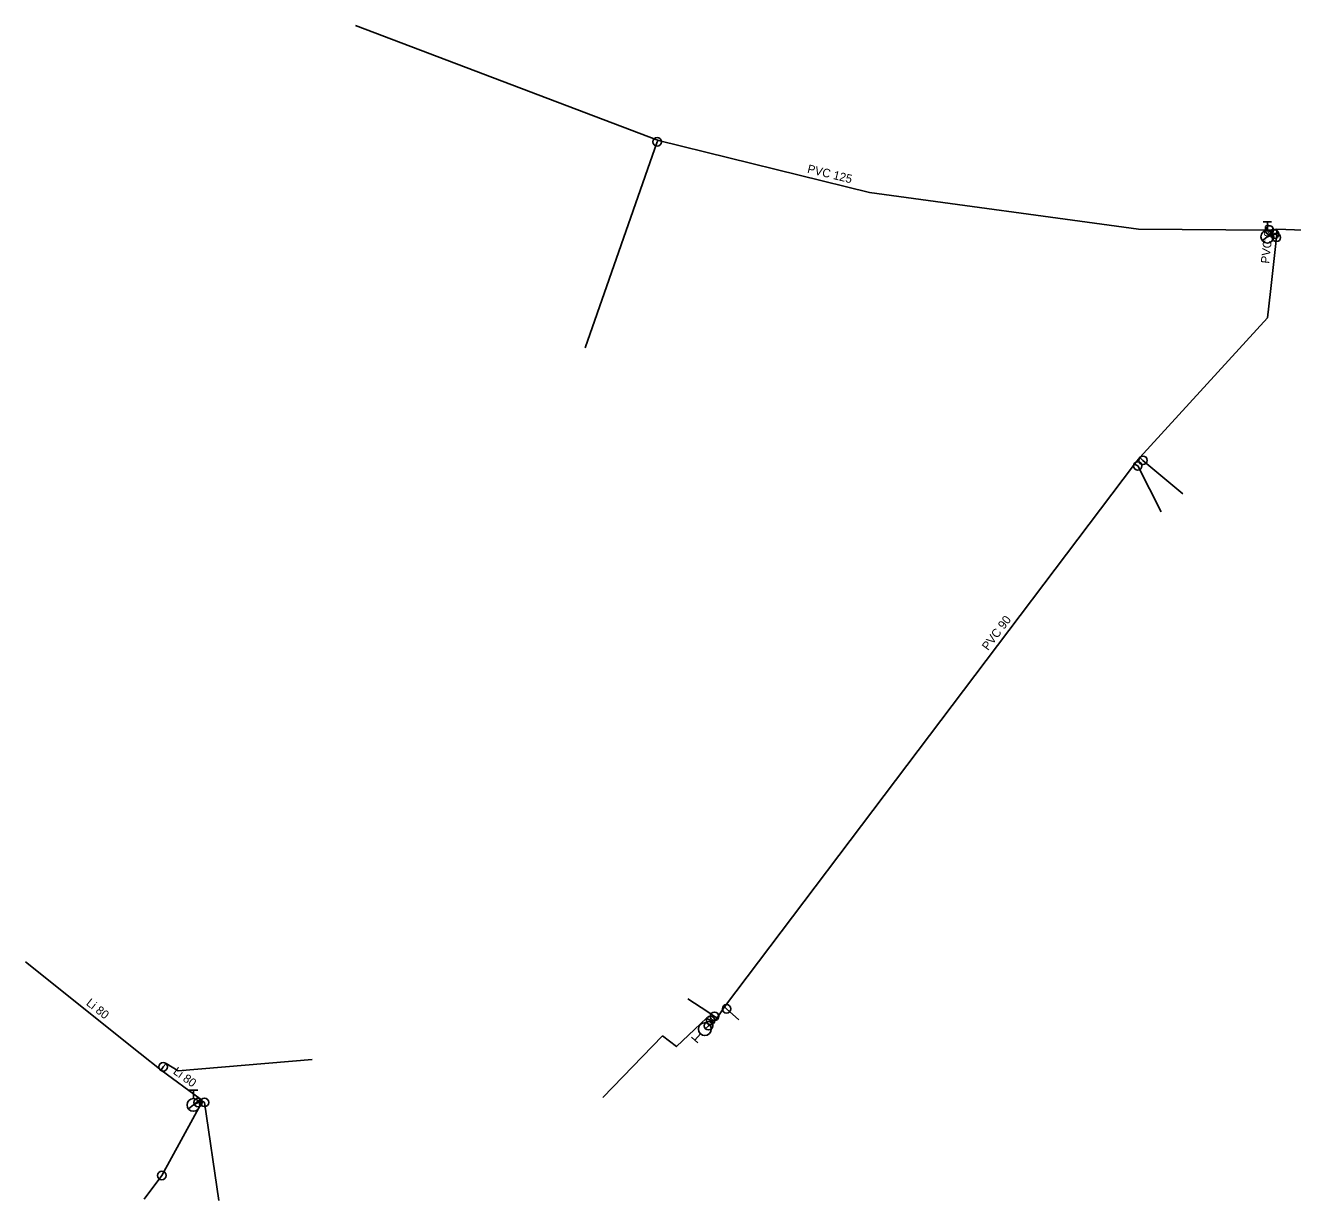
# Model space of a CAD drawing. Extents: x -684724 to -684366, y -1163865 to -1163489.
# Drawn here: x -684724.1 to -684649.7, y -1163702.1 to -1163633.1 of the extents above; entities that cross this region are included whole.
import ezdxf

# ---------------------------------------------------------------- set-up
doc = ezdxf.new("R2010")
doc.units = 0
for name, color, linetype in [('Hydranty', 7, 'Continuous'), ('Popis vodovodních řadů', 7, 'Continuous'), ('Vod přípojky-voda pitná', 7, 'Continuous'), ('Vodovodní řad', 7, 'Continuous'), ('Vodovodní šoupata', 7, 'Continuous')]:
    doc.layers.add(name, color=color, linetype=linetype)

msp = doc.modelspace()

# ---------------------------------------------------------------- linework, layer by layer
at = {"layer": 'Hydranty'}
for p, q in [((-684651.41, -1163644.655), (-684650.91, -1163644.655)), ((-684651.16, -1163645.155), (-684651.16, -1163644.655)), ((-684651.454, -1163645.761), (-684650.864, -1163645.298)), ((-684684.591, -1163692.862), (-684684.958, -1163692.523)), ((-684684.435, -1163692.325), (-684684.774, -1163692.692)), ((-684714.45, -1163695.625), (-684713.95, -1163695.625)), ((-684714.2, -1163696.125), (-684714.2, -1163695.625)), ((-684714.494, -1163696.731), (-684713.904, -1163696.268))]:
    msp.add_line(p, q, dxfattribs=at)
for centre in [(-684651.16, -1163645.53), (-684684.18, -1163692.05), (-684714.2, -1163696.5)]:
    msp.add_circle(centre, 0.375, dxfattribs=at)
at = {"layer": 'Vod přípojky-voda pitná'}
for points in [[(-684686.9, -1163639.88), (-684686.98, -1163639.96), (-684691.21, -1163652.06)], [(-684658.64, -1163658.5), (-684658.46, -1163658.66), (-684656.12, -1163660.63)], [(-684658.96, -1163658.89), (-684658.77, -1163658.99), (-684657.4, -1163661.69)], [(-684684.01, -1163691.03), (-684685.17, -1163690.28)], [(-684683.45, -1163691.39), (-684683.61, -1163691.3), (-684684.01, -1163691.03)], [(-684683.03, -1163690.75), (-684682.9, -1163690.86), (-684682.18, -1163691.51)], [(-684683.67, -1163691.66), (-684683.84, -1163691.54), (-684684.09, -1163691.4), (-684685.85, -1163693.08), (-684686.66, -1163692.44)], [(-684686.66, -1163692.44), (-684690.17, -1163696.06)], [(-684716.1, -1163694.45), (-684715.98, -1163694.26), (-684715.79, -1163694.06), (-684715.1, -1163694.49), (-684707.23, -1163693.84)], [(-684713.66, -1163696.28), (-684716.05, -1163700.64), (-684717.09, -1163702.03)], [(-684713.8, -1163696.14), (-684713.66, -1163696.28), (-684713.55, -1163696.35), (-684712.7, -1163702.12)]]:
    msp.add_lwpolyline(points, dxfattribs=at)
at = {"layer": 'Vodovodní řad'}
for points in [[(-684704.683, -1163633.124), (-684686.9, -1163639.88), (-684674.51, -1163642.93), (-684658.72, -1163645.08), (-684651.04, -1163645.15), (-684650.6, -1163645.08)], [(-684650.6, -1163645.08), (-684650.61, -1163645.43)], [(-684650.6, -1163645.08), (-684647.47, -1163645.21)], [(-684650.74, -1163645.38), (-684651.16, -1163645.53)], [(-684650.63, -1163645.57), (-684650.98, -1163648.74)], [(-684650.61, -1163645.43), (-684650.74, -1163645.38)], [(-684650.61, -1163645.43), (-684650.63, -1163645.57)], [(-684650.98, -1163648.74), (-684651.15, -1163650.29), (-684658.64, -1163658.5), (-684658.96, -1163658.89), (-684683.03, -1163690.75), (-684683.45, -1163691.39), (-684683.67, -1163691.66)], [(-684724.066, -1163688.1), (-684717.32, -1163693.48)], [(-684683.96, -1163691.85), (-684684.18, -1163692.05)], [(-684683.67, -1163691.66), (-684683.96, -1163691.85)], [(-684717.32, -1163693.48), (-684716.1, -1163694.45), (-684713.8, -1163696.14)], [(-684713.93, -1163696.36), (-684714.2, -1163696.5)], [(-684713.8, -1163696.14), (-684713.93, -1163696.36)]]:
    msp.add_lwpolyline(points, dxfattribs=at)
at = {"layer": 'Vodovodní šoupata'}
for centre in [(-684686.98, -1163639.96), (-684651.04, -1163645.15), (-684650.74, -1163645.38), (-684650.63, -1163645.57), (-684658.46, -1163658.66), (-684658.77, -1163658.99), (-684682.9, -1163690.86), (-684683.84, -1163691.54), (-684683.61, -1163691.3), (-684683.96, -1163691.85), (-684715.98, -1163694.26), (-684713.93, -1163696.36), (-684713.55, -1163696.35), (-684716.05, -1163700.64)]:
    msp.add_circle(centre, 0.25, dxfattribs=at)

# ---------------------------------------------------------------- texts
at = {"layer": 'Popis vodovodních řadů'}
for s, rotation, p in [('PVC 125', 346.17068, (-684678.199, -1163641.764)), ('PVC 90', 83.69949, (-684651.053, -1163647.128)), ('PVC 90', 52.92922, (-684667.559, -1163669.857)), ('Li 80', 321.42398, (-684720.537, -1163690.594)), ('Li 80', 323.6922, (-684715.43, -1163694.632))]:
    msp.add_text(s, height=0.5, rotation=rotation, dxfattribs=at).set_placement(p)

doc.saveas('drawing.dxf')
